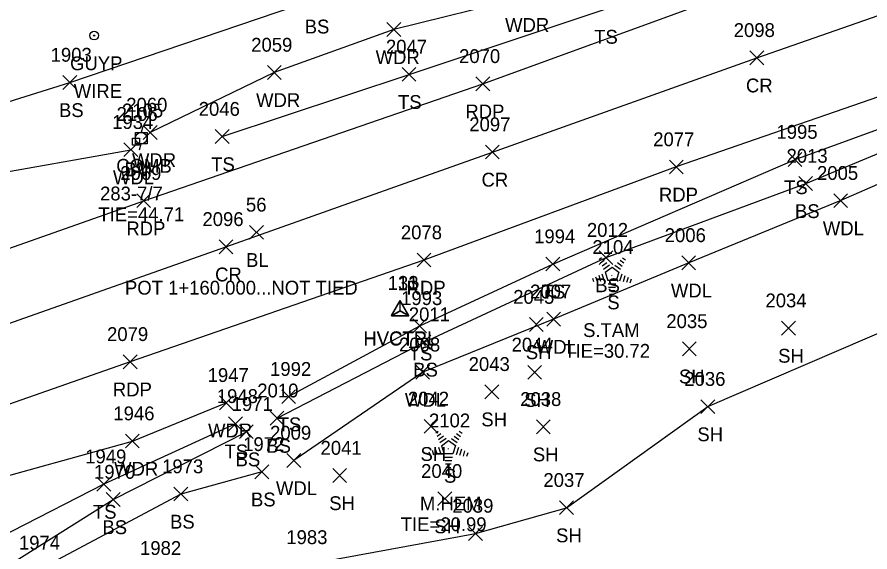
# Model space of a CAD drawing. Extents: x 1526508 to 1531550, y 369926 to 373082.
# Drawn here: x 1531334.3 to 1531457.6, y 370192.4 to 370269.7 of the extents above; entities that cross this region are included whole.
import ezdxf

# ---------------------------------------------------------------- set-up
doc = ezdxf.new("R2010")
doc.units = 0
for name, color, linetype in [('C_A', 7, 'Continuous'), ('C_C', 7, 'Continuous'), ('C_I', 7, 'Continuous'), ('C_TIC', 7, 'Continuous'), ('CPBM', 7, 'Continuous'), ('CPSM', 7, 'Continuous'), ('L_A', 7, 'Continuous'), ('L_C', 7, 'Continuous'), ('L_I', 7, 'Continuous'), ('L_TIC', 7, 'Continuous'), ('LAWA', 7, 'Continuous'), ('LELB', 7, 'Continuous'), ('LSOGP', 7, 'Continuous'), ('LTC', 7, 'Continuous'), ('P_A', 7, 'Continuous'), ('P_I', 7, 'Continuous'), ('P_TIC', 7, 'Continuous'), ('PET', 7, 'Continuous'), ('PRC', 7, 'Continuous'), ('U_A', 7, 'Continuous'), ('U_C', 7, 'Continuous'), ('U_I', 7, 'Continuous'), ('UP', 7, 'Continuous'), ('UPGW', 7, 'Continuous')]:
    doc.layers.add(name, color=color, linetype=linetype)

msp = doc.modelspace()

# ---------------------------------------------------------------- linework, layer by layer
at = {"layer": 'C_TIC'}
for points in [[(1531367.88, 370237.63), (1531369.88, 370239.63)], [(1531369.88, 370237.63), (1531367.88, 370239.63)]]:
    msp.add_lwpolyline(points, dxfattribs=at)
at = {"layer": 'CPBM'}
for p, q in [((1531350.97, 370251.24), (1531350.97, 370252.24)), ((1531350.97, 370252.24), (1531351.97, 370252.24)), ((1531351.47, 370251.74), (1531351.47, 370251.74)), ((1531351.47, 370251.74), (1531351.47, 370251.74)), ((1531351.97, 370252.24), (1531351.97, 370251.24)), ((1531351.97, 370251.24), (1531350.97, 370251.24))]:
    msp.add_line(p, q, dxfattribs=at)
at = {"layer": 'CPSM'}
for p, q in [((1531388.4, 370226.54), (1531389.65, 370228.71)), ((1531388.42, 370226.6), (1531389.67, 370228.76)), ((1531390.9, 370226.54), (1531389.65, 370228.71)), ((1531389.65, 370227.26), (1531389.65, 370228.71)), ((1531390.92, 370226.6), (1531389.67, 370228.76)), ((1531389.67, 370227.32), (1531389.67, 370228.76)), ((1531388.4, 370226.54), (1531389.65, 370227.26)), ((1531388.42, 370226.6), (1531389.67, 370227.32)), ((1531389.65, 370227.26), (1531389.65, 370227.26)), ((1531389.65, 370227.26), (1531390.9, 370226.54)), ((1531389.67, 370227.32), (1531389.67, 370227.32)), ((1531389.67, 370227.32), (1531390.92, 370226.6)), ((1531388.4, 370226.54), (1531390.9, 370226.54)), ((1531388.42, 370226.6), (1531390.92, 370226.6))]:
    msp.add_line(p, q, dxfattribs=at)
at = {"layer": 'L_TIC'}
for points in [[(1531387.76, 370266.94), (1531389.76, 370268.94)], [(1531389.76, 370266.94), (1531387.76, 370268.94)], [(1531370.46, 370260.74), (1531372.46, 370262.74)], [(1531372.46, 370260.74), (1531370.46, 370262.74)], [(1531389.95, 370260.46), (1531391.95, 370262.46)], [(1531391.95, 370260.46), (1531389.95, 370262.46)], [(1531340.88, 370259.29), (1531342.88, 370261.29)], [(1531342.88, 370259.29), (1531340.88, 370261.29)], [(1531352.51, 370252.07), (1531354.51, 370254.07)], [(1531354.51, 370252.07), (1531352.51, 370254.07)], [(1531362.93, 370251.47), (1531364.93, 370253.47)], [(1531364.93, 370251.47), (1531362.93, 370253.47)], [(1531349.71, 370249.57), (1531351.71, 370251.57)], [(1531351.71, 370249.57), (1531349.71, 370251.57)], [(1531445.79, 370248.15), (1531447.79, 370250.15)], [(1531447.79, 370248.15), (1531445.79, 370250.15)], [(1531447.33, 370244.69), (1531449.33, 370246.69)], [(1531449.33, 370244.69), (1531447.33, 370246.69)], [(1531452.39, 370242.21), (1531454.39, 370244.21)], [(1531454.39, 370242.21), (1531452.39, 370244.21)], [(1531418.45, 370233.98), (1531420.45, 370235.98)], [(1531420.45, 370233.98), (1531418.45, 370235.98)], [(1531410.75, 370233.05), (1531412.75, 370235.05)], [(1531412.75, 370233.05), (1531410.75, 370235.05)], [(1531430.41, 370233.22), (1531432.41, 370235.22)], [(1531432.41, 370233.22), (1531430.41, 370235.22)], [(1531410.87, 370225.08), (1531412.87, 370227.08)], [(1531412.87, 370225.08), (1531410.87, 370227.08)], [(1531391.5, 370224.12), (1531393.5, 370226.12)], [(1531393.5, 370224.12), (1531391.5, 370226.12)], [(1531408.36, 370224.3), (1531410.36, 370226.3)], [(1531410.36, 370224.3), (1531408.36, 370226.3)], [(1531444.85, 370223.79), (1531446.85, 370225.79)], [(1531446.85, 370223.79), (1531444.85, 370225.79)], [(1531392.12, 370221.78), (1531394.12, 370223.78)], [(1531394.12, 370221.78), (1531392.12, 370223.78)], [(1531430.51, 370220.79), (1531432.51, 370222.79)], [(1531432.51, 370220.79), (1531430.51, 370222.79)], [(1531391.93, 370217.41), (1531393.93, 370219.41)], [(1531393.93, 370217.41), (1531391.93, 370219.41)], [(1531408.13, 370217.4), (1531410.13, 370219.4)], [(1531410.13, 370217.4), (1531408.13, 370219.4)], [(1531372.54, 370213.88), (1531374.54, 370215.88)], [(1531374.54, 370213.88), (1531372.54, 370215.88)], [(1531401.92, 370214.59), (1531403.92, 370216.59)], [(1531403.92, 370214.59), (1531401.92, 370216.59)], [(1531363.52, 370213), (1531365.52, 370215)], [(1531365.52, 370213), (1531363.52, 370215)], [(1531433.17, 370212.44), (1531435.17, 370214.44)], [(1531435.17, 370212.44), (1531433.17, 370214.44)], [(1531364.84, 370209.96), (1531366.84, 370211.96)], [(1531366.84, 370209.96), (1531364.84, 370211.96)], [(1531370.86, 370210.77), (1531372.86, 370212.77)], [(1531372.86, 370210.77), (1531370.86, 370212.77)], [(1531366.42, 370208.81), (1531368.42, 370210.81)], [(1531368.42, 370208.81), (1531366.42, 370210.81)], [(1531393.12, 370209.59), (1531395.12, 370211.59)], [(1531395.12, 370209.59), (1531393.12, 370211.59)], [(1531409.37, 370209.53), (1531411.37, 370211.53)], [(1531411.37, 370209.53), (1531409.37, 370211.53)], [(1531349.93, 370207.46), (1531351.93, 370209.46)], [(1531351.93, 370207.46), (1531349.93, 370209.46)], [(1531373.28, 370204.66), (1531375.28, 370206.66)], [(1531375.28, 370204.66), (1531373.28, 370206.66)], [(1531368.65, 370203.02), (1531370.65, 370205.02)], [(1531370.65, 370203.02), (1531368.65, 370205.02)], [(1531379.92, 370202.48), (1531381.92, 370204.48)], [(1531381.92, 370202.48), (1531379.92, 370204.48)], [(1531345.81, 370201.24), (1531347.81, 370203.24)], [(1531347.81, 370201.24), (1531345.81, 370203.24)], [(1531347.16, 370199.01), (1531349.16, 370201.01)], [(1531349.16, 370199.01), (1531347.16, 370201.01)], [(1531356.94, 370199.81), (1531358.94, 370201.81)], [(1531358.94, 370199.81), (1531356.94, 370201.81)], [(1531395.13, 370199.13), (1531397.13, 370201.13)], [(1531397.13, 370199.13), (1531395.13, 370201.13)], [(1531412.73, 370197.83), (1531414.73, 370199.83)], [(1531414.73, 370197.83), (1531412.73, 370199.83)], [(1531399.56, 370194.11), (1531401.56, 370196.11)], [(1531401.56, 370194.11), (1531399.56, 370196.11)]]:
    msp.add_lwpolyline(points, dxfattribs=at)
at = {"layer": 'LAWA'}
for points in [[(1531521.76, 370311.94), (1531496.07, 370304.92), (1531465.75, 370292.39), (1531436.88, 370282.15), (1531407.49, 370272.6), (1531388.76, 370267.94), (1531371.46, 370261.74), (1531353.51, 370253.07)], [(1531516.95, 370247.29), (1531513.86, 370259.9), (1531506.38, 370262.26), (1531496.14, 370260.61), (1531477.71, 370253.82), (1531453.39, 370243.21), (1531431.41, 370234.22), (1531411.87, 370226.08), (1531392.93, 370218.41), (1531374.28, 370205.66)], [(1531238.23, 370212.54), (1531260.28, 370219.9), (1531288.7, 370230.78), (1531307.16, 370236.95), (1531328.93, 370246.72), (1531350.71, 370250.57)], [(1531211.59, 370163.28), (1531236.15, 370171.01), (1531264.86, 370180.38), (1531296.6, 370192.07), (1531327.62, 370201.99), (1531350.93, 370208.46), (1531364.52, 370214)]]:
    msp.add_lwpolyline(points, dxfattribs=at)
at = {"layer": 'LELB'}
for points in [[(1531144.65, 370206.06), (1531164.57, 370210.72), (1531180.3, 370218.31), (1531196.61, 370223.05), (1531216.18, 370227.2), (1531246.26, 370234.32), (1531259.5, 370237.9), (1531291.92, 370247.44), (1531321.67, 370253.97), (1531341.88, 370260.29), (1531377.42, 370272.37), (1531403.24, 370281.83), (1531425.1, 370287.02), (1531443.59, 370293.1), (1531470.33, 370300.31), (1531494.61, 370309.28), (1531517.9, 370316.82)], [(1531363.93, 370252.47), (1531390.95, 370261.46), (1531419.32, 370270.89), (1531442.26, 370279.58), (1531461.87, 370286.72), (1531494.43, 370297.22), (1531521.4, 370307.47)], [(1531373.54, 370214.88), (1531392.5, 370225.12), (1531411.75, 370234.05), (1531446.79, 370249.15), (1531471.3, 370258.09), (1531485.65, 370262.9), (1531508.33, 370270.2), (1531510.24, 370265.95)], [(1531371.86, 370211.77), (1531393.12, 370222.78), (1531419.45, 370234.98), (1531448.33, 370245.69), (1531473.07, 370255.96), (1531493.6, 370264.17), (1531507.93, 370268.08), (1531508.86, 370266.64), (1531502.17, 370263.5)], [(1531365.84, 370210.96), (1531346.81, 370202.24), (1531320.04, 370188.54), (1531298.98, 370175.8), (1531270.91, 370160.47), (1531253.9, 370156.3), (1531223.1, 370136.77)], [(1531240.15, 370141.24), (1531255.53, 370153.74), (1531283.26, 370165.55), (1531305.03, 370178.46), (1531329.23, 370188.15), (1531348.16, 370200.01), (1531367.42, 370209.81)], [(1531369.65, 370204.02), (1531357.94, 370200.81), (1531337.22, 370189.77), (1531315.6, 370178.46), (1531299.04, 370171.08), (1531284.23, 370161.86), (1531268.99, 370153.57)]]:
    msp.add_lwpolyline(points, dxfattribs=at)
at = {"layer": 'LSOGP'}
msp.add_lwpolyline([(1531375.89, 370190.57), (1531400.56, 370195.11), (1531413.73, 370198.83), (1531434.17, 370213.44), (1531471.74, 370229.62)], dxfattribs=at)
at = {"layer": 'LTC'}
for p, q in [((1531418.45, 370234.71), (1531418.81, 370234.97)), ((1531418.66, 370234.24), (1531419.19, 370234.63)), ((1531418.87, 370233.78), (1531419.57, 370234.29)), ((1531421.11, 370234.25), (1531421.79, 370233.76)), ((1531421.48, 370234.6), (1531422.03, 370234.2)), ((1531421.85, 370234.95), (1531422.27, 370234.64)), ((1531419.08, 370233.31), (1531419.96, 370233.95)), ((1531419.3, 370232.86), (1531420.32, 370233.59)), ((1531420.32, 370233.59), (1531421.31, 370232.87)), ((1531420.74, 370233.9), (1531421.55, 370233.32)), ((1531417.48, 370231.99), (1531417.64, 370231.52)), ((1531417.94, 370232.2), (1531418.15, 370231.55)), ((1531418.39, 370232.42), (1531418.67, 370231.59)), ((1531418.85, 370232.64), (1531419.18, 370231.62)), ((1531419.3, 370232.86), (1531419.69, 370231.66)), ((1531421.31, 370232.87), (1531420.92, 370231.66)), ((1531421.75, 370232.6), (1531421.41, 370231.56)), ((1531422.19, 370232.34), (1531421.91, 370231.46)), ((1531422.64, 370232.09), (1531422.4, 370231.37)), ((1531423.08, 370231.84), (1531422.9, 370231.27)), ((1531420.92, 370231.66), (1531419.69, 370231.66)), ((1531420.88, 370231.16), (1531419.74, 370231.16)), ((1531420.8, 370230.66), (1531419.81, 370230.66)), ((1531420.72, 370230.16), (1531419.88, 370230.16)), ((1531420.63, 370229.66), (1531419.96, 370229.66)), ((1531394.81, 370209.64), (1531395.16, 370209.9)), ((1531395.01, 370209.18), (1531395.54, 370209.56)), ((1531397.83, 370209.54), (1531398.38, 370209.14)), ((1531398.2, 370209.88), (1531398.62, 370209.58)), ((1531395.22, 370208.71), (1531395.93, 370209.22)), ((1531395.43, 370208.25), (1531396.31, 370208.88)), ((1531395.66, 370207.79), (1531396.67, 370208.53)), ((1531396.67, 370208.53), (1531397.67, 370207.8)), ((1531397.09, 370208.84), (1531397.9, 370208.25)), ((1531397.46, 370209.19), (1531398.14, 370208.69)), ((1531394.29, 370207.14), (1531394.5, 370206.49)), ((1531394.75, 370207.36), (1531395.02, 370206.52)), ((1531395.2, 370207.57), (1531395.53, 370206.55)), ((1531395.66, 370207.79), (1531396.05, 370206.6)), ((1531397.67, 370207.8), (1531397.28, 370206.6)), ((1531398.1, 370207.53), (1531397.77, 370206.49)), ((1531398.55, 370207.28), (1531398.26, 370206.4)), ((1531398.99, 370207.03), (1531398.76, 370206.3)), ((1531393.84, 370206.92), (1531393.99, 370206.45)), ((1531397.28, 370206.6), (1531396.05, 370206.6)), ((1531397.24, 370206.1), (1531396.09, 370206.1)), ((1531399.44, 370206.78), (1531399.25, 370206.21)), ((1531397.15, 370205.6), (1531396.17, 370205.6)), ((1531397.07, 370205.1), (1531396.24, 370205.1)), ((1531396.99, 370204.6), (1531396.31, 370204.6))]:
    msp.add_line(p, q, dxfattribs=at)
at = {"layer": 'P_TIC'}
for points in [[(1531440.26, 370262.86), (1531442.26, 370264.86)], [(1531442.26, 370262.86), (1531440.26, 370264.86)], [(1531400.62, 370259.1), (1531402.62, 370261.1)], [(1531402.62, 370259.1), (1531400.62, 370261.1)], [(1531402.01, 370249.24), (1531404.01, 370251.24)], [(1531404.01, 370249.24), (1531402.01, 370251.24)], [(1531428.61, 370247.08), (1531430.61, 370249.08)], [(1531430.61, 370247.08), (1531428.61, 370249.08)], [(1531351.57, 370242.2), (1531353.57, 370244.2)], [(1531353.57, 370242.2), (1531351.57, 370244.2)], [(1531363.47, 370235.54), (1531365.47, 370237.54)], [(1531365.47, 370235.54), (1531363.47, 370237.54)], [(1531392.11, 370233.63), (1531394.11, 370235.63)], [(1531394.11, 370233.63), (1531392.11, 370235.63)], [(1531349.62, 370218.92), (1531351.62, 370220.92)], [(1531351.62, 370218.92), (1531349.62, 370220.92)]]:
    msp.add_lwpolyline(points, dxfattribs=at)
at = {"layer": 'PET'}
for points in [[(1531036.19, 370150.91), (1531061.97, 370155.43), (1531104.8, 370164.58), (1531143.1, 370174.02), (1531180.11, 370184.91), (1531218.48, 370196.81), (1531260.06, 370210.9), (1531302.03, 370225.36), (1531352.57, 370243.2), (1531401.62, 370260.1), (1531448.12, 370277.05), (1531486.93, 370290.59), (1531531.91, 370306.21)], [(1531538.54, 370286.02), (1531506.28, 370274.48), (1531462.76, 370259.55), (1531429.61, 370248.08), (1531393.11, 370234.63), (1531350.62, 370219.92), (1531310.67, 370205.95), (1531271.31, 370192.3), (1531228.45, 370178.01), (1531188.4, 370165.28), (1531155.96, 370155.78), (1531116.2, 370145.37), (1531081.97, 370137.61), (1531057.06, 370132.93), (1531039.15, 370130.45)]]:
    msp.add_lwpolyline(points, dxfattribs=at)
at = {"layer": 'PRC'}
msp.add_lwpolyline([(1531037.76, 370140.53), (1531081.39, 370148.17), (1531130.61, 370160.04), (1531176.3, 370172.81), (1531216.72, 370185.49), (1531265.37, 370201.61), (1531315.14, 370219.14), (1531364.47, 370236.54), (1531403.01, 370250.24), (1531441.26, 370263.86), (1531484.78, 370279.08), (1531519.83, 370291.48), (1531535.78, 370296.89)], dxfattribs=at)
at = {"layer": 'UP'}
for p, q in [((1531352.46, 370253.91), (1531352.21, 370253.07)), ((1531351.38, 370251.41), (1531351.38, 370253.07)), ((1531351.38, 370253.07), (1531353.05, 370253.07)), ((1531353.05, 370253.07), (1531353.05, 370251.41)), ((1531352.21, 370252.24), (1531352.21, 370252.24)), ((1531353.05, 370251.41), (1531351.38, 370251.41)), ((1531351.96, 370250.57), (1531352.21, 370251.41))]:
    msp.add_line(p, q, dxfattribs=at)
msp.add_circle((1531352.21, 370252.24), 0.833, dxfattribs=at)
at = {"layer": 'UPGW'}
for radius in [0.625, 0.0833]:
    msp.add_circle((1531345.41, 370267.06), radius, dxfattribs=at)

# ---------------------------------------------------------------- texts
at = {"layer": 'C_A'}
for s, p in [('BM', (1531349.79, 370246.74)), ('BL', (1531367.37, 370233.63)), ('HVCTRL', (1531384.34, 370222.26)), ('HVCTRL', (1531384.36, 370222.32))]:
    msp.add_text(s, height=2, dxfattribs=at).set_placement(p)
at = {"layer": 'C_C'}
msp.add_text('POT 1+160.000...NOT TIED', height=2, dxfattribs=at).set_placement((1531349.86, 370229.63))
at = {"layer": 'C_I'}
for s, p in [('2106', (1531348.65, 370254.74)), ('56', (1531367.36, 370241.63)), ('133', (1531387.87, 370230.32)), ('11', (1531389.32, 370230.26))]:
    msp.add_text(s, height=2, dxfattribs=at).set_placement(p)
at = {"layer": 'L_A'}
for s, p in [('BS', (1531375.86, 370267.37)), ('WDR', (1531404.85, 370267.6)), ('TS', (1531417.73, 370265.89)), ('WDR', (1531386.12, 370262.94)), ('WDR', (1531368.83, 370256.74)), ('TS', (1531389.36, 370256.46)), ('BS', (1531340.32, 370255.29)), ('WDR', (1531350.87, 370248.07)), ('TS', (1531362.33, 370247.47)), ('WDL', (1531348.13, 370245.57)), ('TS', (1531445.2, 370244.15)), ('BS', (1531446.78, 370240.69)), ('WDL', (1531450.81, 370238.21)), ('BS', (1531417.89, 370229.98)), ('TS', (1531410.15, 370229.05)), ('WDL', (1531428.83, 370229.22)), ('S', (1531419.64, 370227.5)), ('WDL', (1531409.29, 370221.08)), ('TS', (1531390.91, 370220.12)), ('SH', (1531407.85, 370220.3)), ('SH', (1531444.34, 370219.79)), ('BS', (1531391.56, 370217.78)), ('SH', (1531430, 370216.79)), ('WDL', (1531390.35, 370213.41)), ('SH', (1531407.62, 370213.4)), ('SH', (1531401.41, 370210.59)), ('WDR', (1531361.88, 370209)), ('TS', (1531371.95, 370209.88)), ('SH', (1531432.66, 370208.44)), ('BS', (1531370.3, 370206.77)), ('TS', (1531364.25, 370205.96)), ('SH', (1531392.61, 370205.59)), ('SH', (1531408.86, 370205.53)), ('BS', (1531365.86, 370204.81)), ('WDR', (1531348.29, 370203.46)), ('S', (1531396, 370202.44)), ('WDL', (1531371.7, 370200.66)), ('BS', (1531368.09, 370199.02)), ('SH', (1531379.41, 370198.48)), ('TS', (1531345.22, 370197.24)), ('BS', (1531356.38, 370195.81)), ('SH', (1531394.62, 370195.13)), ('BS', (1531346.6, 370195.01)), ('SH', (1531412.22, 370193.83))]:
    msp.add_text(s, height=2, dxfattribs=at).set_placement(p)
at = {"layer": 'L_C'}
for s, p in [('S.TAM', (1531416.13, 370223.5)), ('TIE=30.72', (1531413.4, 370220.5)), ('M.HEM', (1531392.52, 370198.44)), ('TIE=20.99', (1531389.75, 370195.44))]:
    msp.add_text(s, height=2, dxfattribs=at).set_placement(p)
at = {"layer": 'L_I'}
for s, p in [('2059', (1531368.12, 370264.74)), ('2047', (1531387.61, 370264.46)), ('1903', (1531339.11, 370263.29)), ('2060', (1531350.04, 370256.07)), ('2046', (1531360.53, 370255.47)), ('1934', (1531348.01, 370253.57)), ('1995', (1531444.1, 370252.15)), ('2013', (1531445.56, 370248.69)), ('2005', (1531449.97, 370246.21)), ('2012', (1531416.68, 370237.98)), ('2006', (1531427.94, 370237.22)), ('1994', (1531409.05, 370237.05)), ('2104', (1531417.48, 370235.5)), ('2007', (1531408.46, 370229.08)), ('1993', (1531389.81, 370228.12)), ('2045', (1531406.02, 370228.3)), ('2034', (1531442.51, 370227.79)), ('2011', (1531390.92, 370225.78)), ('2035', (1531428.17, 370224.79)), ('2008', (1531389.51, 370221.41)), ('2044', (1531405.79, 370221.4)), ('2043', (1531399.58, 370218.59)), ('1992', (1531370.85, 370217.88)), ('1947', (1531361.82, 370217)), ('2036', (1531430.77, 370216.44)), ('1948', (1531363.15, 370213.96)), ('2010', (1531369, 370214.77)), ('1971', (1531365.29, 370212.81)), ('2042', (1531390.79, 370213.59)), ('2038', (1531407.03, 370213.53)), ('1946', (1531348.18, 370211.46)), ('2102', (1531393.84, 370210.44)), ('2009', (1531370.85, 370208.66)), ('1972', (1531366.96, 370207.02)), ('2041', (1531378.15, 370206.48)), ('1949', (1531344.11, 370205.24)), ('1973', (1531355.24, 370203.81)), ('1970', (1531345.38, 370203.01)), ('2040', (1531392.7, 370203.13)), ('2037', (1531410.39, 370201.83)), ('2039', (1531397.21, 370198.11)), ('1974', (1531334.52, 370192.77)), ('1983', (1531373.2, 370193.57)), ('1982', (1531352.04, 370192))]:
    msp.add_text(s, height=2, dxfattribs=at).set_placement(p)
at = {"layer": 'LTC'}
for p in [(1531420.2, 370232.6), (1531396.55, 370207.54)]:
    msp.add_text('.', height=1.04, rotation=270, dxfattribs=at).set_placement(p)
at = {"layer": 'P_A'}
for s, p in [('CR', (1531439.69, 370258.86)), ('RDP', (1531399.1, 370255.1)), ('CR', (1531401.44, 370245.24)), ('RDP', (1531427.1, 370243.08)), ('RDP', (1531350.06, 370238.2)), ('CR', (1531362.9, 370231.54)), ('RDP', (1531390.6, 370229.63)), ('RDP', (1531348.11, 370214.92))]:
    msp.add_text(s, height=2, dxfattribs=at).set_placement(p)
at = {"layer": 'P_I'}
for s, p in [('2098', (1531437.92, 370266.86)), ('2070', (1531398.19, 370263.1)), ('2097', (1531399.67, 370253.24)), ('2077', (1531426.27, 370251.08)), ('2069', (1531349.18, 370246.2)), ('2096', (1531361.07, 370239.54)), ('2078', (1531389.77, 370237.63)), ('2079', (1531347.27, 370222.92))]:
    msp.add_text(s, height=2, dxfattribs=at).set_placement(p)
at = {"layer": 'U_A'}
for s, p in [('GUYP', (1531341.92, 370262.06)), ('COMB', (1531348.6, 370247.24))]:
    msp.add_text(s, height=2, dxfattribs=at).set_placement(p)
at = {"layer": 'U_C'}
for s, p in [('WIRE', (1531342.45, 370258.06)), ('283-7/7', (1531346.26, 370243.24)), ('TIE=44.71', (1531346.01, 370240.24))]:
    msp.add_text(s, height=2, dxfattribs=at).set_placement(p)
at = {"layer": 'U_I'}
msp.add_text('2105', height=2, dxfattribs=at).set_placement((1531349.44, 370255.24))

doc.saveas('drawing.dxf')
